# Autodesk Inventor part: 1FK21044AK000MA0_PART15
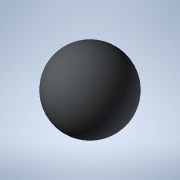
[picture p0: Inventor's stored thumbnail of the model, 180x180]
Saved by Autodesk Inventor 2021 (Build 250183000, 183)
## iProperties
Created: 2025-04
Part Number: 1FK21044AK000MA0_PART15
Material: Generic
Catalog Web Link: www.3dfindit.com
Description: -Servo synchronous motor
Document SubType Name: Modeling
Designer: psAdmin
Mass: 0.137258 g
Surface Area: 1.2868 cm^2
Volume: 0.137258 cm^3
Density: 1 g/cm^3
Appearance: PSOLRGB-212-217-219
Category: PARTsolutions
Title: 1FK21044AK000MA0_PART15
Author: Cadenas PARTsolutions
Comments: Servo synchronous motor
Sending System: PARTsolutions
Preprocessor: ST-DEVELOPER v19.3
PSOL_IDENT_0: {$CADENAS_DATA/23d-libs/siemens_ag/_cat_/87/f4/1fk21044ak000ma0.prj},216 {VTYP=3D},{NB=1FK21044AK000
PSOL_IDENT_1: MA0_PART15},{LINA=1FK21044AK000MA0_PART15},{NN=1FK21044AK000MA0_PART15},{NOPRJ=TRUE},{DATE=19.08.202
PSOL_IDENT_2: 5 14:00:48},{GEOMDATE=30.07.2025 02:00:50},{VERSION=},{LINEID=10},{WBVAR=},{WBNUMERIC=}  {NB=1FK2104
PSOL_IDENT_3: 4AK000MA0_PART15},{LINA=1FK21044AK000MA0_PART15},{KT=DUMMY},{PREVIEW=../../../_pool_/cb/72/p_d211_xx
PSOL_IDENT_4: _00434j.png},{DESCSHORT=SIMOTICS S-1FK2 HD, SINAMICS S210 3AC 400V-480V, 0.95 Nm, 6000 rpm},{DESCLON
PSOL_IDENT_5: G=SIMOTICS S-1FK2 HD servo motor M0=1.27 Nm; PN = 0.6 kW at nN=6000 rpm (380-480 V); PN = 0.4 kW at
PSOL_IDENT_6: nN=3000 rpm (200-240 V); degree of protection IP64; cylindrical shaft D19x40mm; absolute encoder 22-
PSOL_IDENT_7: bit + 12-bit multiturn (encoder AM22DQC); with OCC interface; plug size M17, rotatable; SIMOTICS S-1
PSOL_IDENT_8: FK2 servomotorfor a wide range of uses in industrial environments. SIMOTICS S‑1FK2 servomotors are c
PSOL_IDENT_9: ompact synchronous motors with a high dynamic performance that set themselves apart as a result of t
PSOL_IDENT_10: heir high power density, degree of protection and overload capability. The motors are available in t
PSOL_IDENT_11: wo variants: as High Dynamic variant (highest dynamic performance as a result of the low intrinsic m
PSOL_IDENT_12: oment of inertia for applications demanding a high dynamic performance with low moved masses) - and
PSOL_IDENT_13: as Compact variant (precise and stable closed-loop control for medium up to large moved masses as a
PSOL_IDENT_14: result of a medium intrinsic moment of inertia). SIMOTICSS‑1FK2 servomotors fully exploit their stre
PSOL_IDENT_15: ngths in a system with the SINAMICSS210 frequency converter and simple connection using the one cabl
PSOL_IDENT_16: e connection (OCC). Advantages include the short control and positioning times, fast and precise cor
PSOL_IDENT_17: rection of disturbing quantities as well as stable control with a high dynamic performance. The serv
PSOL_IDENT_18: o motors can be configured to address a wide range of requirements. For example with and without hol
PSOL_IDENT_19: ding brake, IP64 or IP65 degree of protection, singleturn or multiturn absolute encoders - to name j
PSOL_IDENT_20: ust a few. Further, the servomotors are available in different shaft heights extending from 20 to 10
PSOL_IDENT_21: 0. A shaft sealing ring is available to achieve an IP65 degree of protection and for subsequent moun
PSOL_IDENT_22: ting at the motor or as spare part. SIMOTICS - the optimum motor for each and every motion control a
PSOL_IDENT_23: pplication.},{INTNO=195125056312},{SUPPLIERALTNO=1FK2104-4AK00-0MA0},{MANUID=1FK21044AK000MA0},{MANU
PSOL_IDENT_24: NAME=Siemens},{MANUTYPEDESC=Synchronous motor 1FK2-HD 1,27 Nm},{AAU732=SIMOTICS},{AAO057=S-1FK2},{AA
PSOL_IDENT_25: U734=SIMOTICS S-1FK2 HD servo motor M0=1.27 Nm; PN = 0.6 kW at nN=6000 rpm (380-480 V); PN = 0.4 kW
PSOL_IDENT_26: at nN=3000 rpm (200-240 V); degree of protection IP64; cylindrical shaft D19x40mm; absolute encoder
PSOL_IDENT_27: 22-bit + 12-bit multiturn (encoder AM22DQC); with OCC interface; plug size M17, rotatable;},{AAW338=
PSOL_IDENT_28: Synchronous motor 1FK2-HD 1,27 Nm},{AAO742=SIMOTICS},{AAO663=4042948690994},{NOCUPEROU=1},{PRICEQUAN
PSOL_IDENT_29: TITY=1},{QUANTITYMIN=1},{QUANTITYINT=1},{CTN=85015100},{COO=DE},{AAO676=1FK2104-4AK00-0MA0},{AAO677=
PSOL_IDENT_30: Siemens AG},{ORDERUNIT=C62},{CONTENTUNIT=C62}
NB: 1FK21044AK000MA0_PART15
NT: Servo synchronous motor
NBSYN: $MANUID._PART15
LINA: 1FK21044AK000MA0_PART15
CATALOG: SIEMENS
PREVIEW: ../../../_pool_/cb/72/p_d211_xx_00434j.png
DESCSHORT: SIMOTICS S-1FK2 HD, SINAMICS S210 3AC 400V-480V, 0.95 Nm, 6000 rpm
DESCLONG: SIMOTICS S-1FK2 HD servo motor M0=1.27 Nm; PN = 0.6 kW at nN=6000 rpm (380-480 V); PN = 0.4 kW at nN=3000 rpm (200-240 V); degree of protection IP64; cylindrica
INTNO: 195125056312
SUPPLIERALTNO: 1FK2104-4AK00-0MA0
MANUID: 1FK21044AK000MA0
MANUNAME: Siemens
MANUTYPEDESC: Synchronous motor 1FK2-HD 1,27 Nm
AAU732: SIMOTICS
AAO057: S-1FK2
AAU734: SIMOTICS S-1FK2 HD servo motor M0=1.27 Nm; PN = 0.6 kW at nN=6000 rpm (380-480 V); PN = 0.4 kW at nN=3000 rpm (200-240 V); degree of protection IP64; cylindrica
AAW338: Synchronous motor 1FK2-HD 1,27 Nm
AAO742: SIMOTICS
AAO663: 4042948690994.0
NOCUPEROU: 1
PRICEQUANTITY: 1
QUANTITYMIN: 1
QUANTITYINT: 1
CTN: 85015100
COO: DE
ARTICLENO: 1FK21044AK000MA0_PART15
BOMINFO: 1FK21044AK000MA0_PART15
CREATOR: CADENAS GmbH
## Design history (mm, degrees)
feature "2025_04_17_15_37_40_0588"
body "Solid1"
